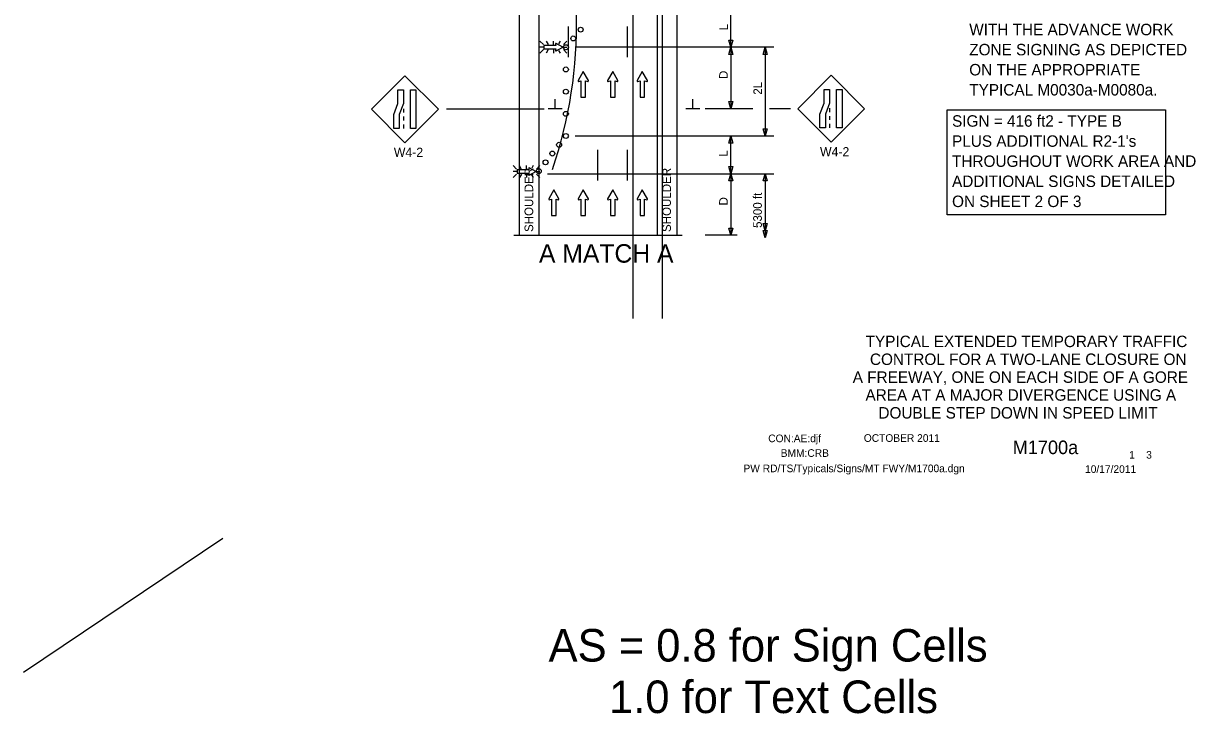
# Model space of a CAD drawing. Extents: x 16486 to 19505, y 5576 to 6998.
# Drawn here: x 16486 to 17438, y 5738 to 6298 of the extents above; entities that cross this region are included whole.
import ezdxf

# ---------------------------------------------------------------- set-up
doc = ezdxf.new("R2010")
doc.units = 0
for name, color, linetype in [('ALI_LEGAL_EX', 7, 'Continuous'), ('BORDER', 7, 'Continuous'), ('BORDER_SIGNAL_WO', 7, 'Continuous'), ('MT_SCRATCH_LEVEL_E', 7, 'Continuous'), ('PAVT_EDGE_EX', 7, 'Continuous'), ('TRAFFIC_SIGNS_PR', 7, 'Continuous'), ('TYPICAL_TEXT_DIMEN_EX', 7, 'Continuous'), ('TYPICAL_TEXT_DIMEN_PR', 7, 'Continuous')]:
    doc.layers.add(name, color=color, linetype=linetype)

msp = doc.modelspace()

# ---------------------------------------------------------------- linework, layer by layer
at = {"layer": 'ALI_LEGAL_EX'}
for p, q in [((16980.68, 6974.12), (16980.68, 6155.98)), ((17004.68, 6974.12), (17004.68, 6155.98)), ((16980.68, 6922.21), (16980.68, 6058.3)), ((17004.68, 6922.21), (17004.68, 6058.3))]:
    msp.add_line(p, q, dxfattribs=at)
for points in [[(16928.4, 6270.33), (16928.4, 6295.33)], [(16976.4, 6270.33), (16976.4, 6295.33)], [(16952.4, 6170.33), (16952.4, 6195.33)], [(16976.4, 6170.33), (16976.4, 6195.33)]]:
    msp.add_lwpolyline(points, dxfattribs=at)
msp.add_arc((16571.06, 6296.99), 364, 341.14744, 21.33821, dxfattribs=at)
at = {"layer": 'MT_SCRATCH_LEVEL_E'}
for p, q in [((16940.5, 6258.7), (16936.39, 6251.46)), ((16944.64, 6251.46), (16940.5, 6258.7)), ((16964.4, 6258.7), (16960.29, 6251.46)), ((16968.55, 6251.46), (16964.4, 6258.7)), ((16988.45, 6258.7), (16984.34, 6251.46)), ((16992.6, 6251.46), (16988.45, 6258.7)), ((16936.87, 6250.78), (16938.64, 6251.09)), ((16938.64, 6251.09), (16938.64, 6237.84)), ((16942.39, 6237.84), (16942.39, 6251.09)), ((16942.39, 6251.09), (16944.16, 6250.78)), ((16960.77, 6250.78), (16962.55, 6251.09)), ((16962.55, 6251.09), (16962.55, 6237.84)), ((16966.29, 6237.84), (16966.29, 6251.09)), ((16966.29, 6251.09), (16968.07, 6250.78)), ((16984.82, 6250.78), (16986.6, 6251.09)), ((16986.6, 6251.09), (16986.6, 6237.84)), ((16990.34, 6237.84), (16990.34, 6251.09)), ((16990.34, 6251.09), (16992.12, 6250.78)), ((16938.64, 6237.84), (16942.39, 6237.84)), ((16962.55, 6237.84), (16966.29, 6237.84)), ((16986.6, 6237.84), (16990.34, 6237.84)), ((16916.59, 6162.72), (16912.48, 6155.48)), ((16920.74, 6155.48), (16916.59, 6162.72)), ((16940.5, 6162.72), (16936.39, 6155.48)), ((16944.64, 6155.48), (16940.5, 6162.72)), ((16964.4, 6162.72), (16960.29, 6155.48)), ((16968.55, 6155.48), (16964.4, 6162.72)), ((16988.45, 6162.72), (16984.34, 6155.48)), ((16992.6, 6155.48), (16988.45, 6162.72)), ((16912.96, 6154.79), (16914.74, 6155.11)), ((16914.74, 6155.11), (16914.74, 6141.85)), ((16918.48, 6141.85), (16918.48, 6155.11)), ((16918.48, 6155.11), (16920.26, 6154.79)), ((16936.87, 6154.79), (16938.64, 6155.11)), ((16938.64, 6155.11), (16938.64, 6141.85)), ((16942.39, 6141.85), (16942.39, 6155.11)), ((16942.39, 6155.11), (16944.16, 6154.79)), ((16960.77, 6154.79), (16962.55, 6155.11)), ((16962.55, 6155.11), (16962.55, 6141.85)), ((16966.29, 6141.85), (16966.29, 6155.11)), ((16966.29, 6155.11), (16968.07, 6154.79)), ((16984.82, 6154.79), (16986.6, 6155.11)), ((16986.6, 6155.11), (16986.6, 6141.85)), ((16990.34, 6141.85), (16990.34, 6155.11)), ((16990.34, 6155.11), (16992.12, 6154.79)), ((16914.74, 6141.85), (16918.48, 6141.85)), ((16938.64, 6141.85), (16942.39, 6141.85)), ((16962.55, 6141.85), (16966.29, 6141.85)), ((16986.6, 6141.85), (16990.34, 6141.85))]:
    msp.add_line(p, q, dxfattribs=at)
for centre, start, end in [((16936.79, 6251.24), 150.42484, 279.96381), ((16944.23, 6251.24), 260.03619, 29.77312), ((16960.7, 6251.24), 150.42484, 279.96381), ((16968.14, 6251.24), 260.03619, 29.77312), ((16984.75, 6251.24), 150.42484, 279.96381), ((16992.19, 6251.24), 260.03619, 29.77312), ((16912.89, 6155.25), 150.42484, 279.96381), ((16920.33, 6155.25), 260.03619, 29.77312), ((16936.79, 6155.25), 150.42484, 279.96381), ((16944.23, 6155.25), 260.03619, 29.77312), ((16960.7, 6155.25), 150.42484, 279.96381), ((16968.14, 6155.25), 260.03619, 29.77312), ((16984.75, 6155.25), 150.42484, 279.96381), ((16992.19, 6155.25), 260.03619, 29.77312)]:
    msp.add_arc(centre, 0.463, start, end, dxfattribs=at)
at = {"layer": 'PAVT_EDGE_EX'}
for p, q in [((16888.4, 6480.53), (16888.4, 6125.9)), ((16904.4, 6480.53), (16904.4, 6125.9)), ((17000.4, 6480.53), (17000.4, 6125.9)), ((17016.4, 6480.53), (17016.4, 6125.9))]:
    msp.add_line(p, q, dxfattribs=at)
at = {"layer": 'TRAFFIC_SIGNS_PR'}
for p, q in [((16908.17, 6280.57), (16905.35, 6283.39)), ((16910.47, 6283.39), (16912.1, 6280.57)), ((16916.26, 6280.57), (16916.26, 6283.39)), ((16921.73, 6283.39), (16920.52, 6281.3)), ((16927.16, 6283.39), (16924.35, 6280.57)), ((16908.17, 6278.54), (16905.35, 6278.54)), ((16908.17, 6276.51), (16905.35, 6273.69)), ((16912.12, 6276.51), (16910.5, 6273.69)), ((16916.26, 6276.51), (16916.26, 6273.69)), ((16920.44, 6275.87), (16921.7, 6273.69)), ((16924.35, 6278.54), (16927.16, 6278.54)), ((16927.16, 6273.69), (16924.35, 6276.51)), ((16795.76, 6255.3), (16768.61, 6228.14)), ((16822.91, 6228.14), (16795.76, 6255.3)), ((17141.78, 6255.72), (17114.62, 6228.57)), ((17168.93, 6228.57), (17141.78, 6255.72)), ((16768.61, 6228.14), (16795.76, 6200.99)), ((16794.51, 6228.64), (16794.51, 6225.44)), ((16795.76, 6200.99), (16822.91, 6228.14)), ((17114.62, 6228.57), (17141.78, 6201.41)), ((17140.53, 6229.06), (17140.53, 6225.86)), ((17141.78, 6201.41), (17168.93, 6228.57)), ((16794.51, 6222.24), (16794.51, 6219.04)), ((16794.51, 6215.84), (16794.51, 6212.64)), ((17140.53, 6222.66), (17140.53, 6219.46)), ((17140.53, 6216.26), (17140.53, 6213.06)), ((16886.3, 6179.62), (16883.48, 6182.44)), ((16886.3, 6177.59), (16883.48, 6177.59)), ((16888.6, 6182.44), (16890.23, 6179.62)), ((16894.39, 6179.62), (16894.39, 6182.44)), ((16899.86, 6182.44), (16898.65, 6180.35)), ((16905.29, 6182.44), (16902.47, 6179.62)), ((16902.47, 6177.59), (16905.29, 6177.59)), ((16886.3, 6175.56), (16883.48, 6172.74)), ((16890.25, 6175.56), (16888.62, 6172.74)), ((16894.39, 6175.56), (16894.39, 6172.74)), ((16898.57, 6174.92), (16899.83, 6172.74)), ((16905.29, 6172.74), (16902.47, 6175.56))]:
    msp.add_line(p, q, dxfattribs=at)
for points in [[(16918.09, 6281.22), (16918.32, 6279.93), (16908.59, 6279.93), (16908.59, 6277.18), (16918.32, 6277.18), (16918.08, 6275.88)], [(16918.59, 6275.53), (16923.9, 6278.54), (16918.59, 6281.58)], [(16896.21, 6180.27), (16896.44, 6178.97), (16886.72, 6178.97), (16886.72, 6176.23), (16896.44, 6176.23), (16896.21, 6174.93)], [(16896.71, 6174.57), (16902.02, 6177.59), (16896.71, 6180.63)]]:
    msp.add_lwpolyline(points, dxfattribs=at)
for points in [[(16794.51, 6243.88), (16794.51, 6232.7), (16791.17, 6223.82), (16791.17, 6212.64), (16786.67, 6212.64), (16786.67, 6223.82), (16790.02, 6232.7), (16790.02, 6243.88)], [(16804.65, 6243.88), (16804.65, 6212.64), (16800.15, 6212.64), (16800.15, 6243.88)], [(17140.53, 6244.3), (17140.53, 6233.12), (17137.19, 6224.24), (17137.19, 6213.06), (17132.69, 6213.06), (17132.69, 6224.24), (17136.04, 6233.12), (17136.04, 6244.3)], [(17150.67, 6244.3), (17150.67, 6213.06), (17146.17, 6213.06), (17146.17, 6244.3)]]:
    msp.add_lwpolyline(points, close=True, dxfattribs=at)
for centre in [(16938.4, 6292.75), (16932.4, 6285.61), (16926.4, 6278.47), (16926.4, 6260.47), (16926.4, 6242.47), (16926.4, 6224.47), (16926.4, 6206.47), (16920.9, 6199.34), (16909.91, 6185.08), (16915.4, 6192.21), (16904.41, 6177.96)]:
    msp.add_circle(centre, 2, dxfattribs=at)
for centre, start, end in [((16918.42, 6281.28), 61.48329, 189.95933), ((16918.42, 6275.82), 170.73078, 298.89165), ((16896.55, 6180.33), 61.48329, 189.95933), ((16896.55, 6174.87), 170.73078, 298.89165)]:
    msp.add_arc(centre, 0.341, start, end, dxfattribs=at)
at = {"layer": 'TYPICAL_TEXT_DIMEN_EX'}
msp.add_lwpolyline([(17235.9, 6227.83), (17413.17, 6227.83), (17413.17, 6142.51), (17235.9, 6142.51)], close=True, dxfattribs=at)
at = {"layer": 'TYPICAL_TEXT_DIMEN_PR'}
for p, q in [((17060.4, 6278.47), (17060.4, 6307.03)), ((17060.4, 6278.47), (17058.83, 6284.33)), ((17058.83, 6284.33), (17060.4, 6284.33)), ((17060.4, 6284.33), (17061.97, 6284.33)), ((17061.97, 6284.33), (17060.4, 6278.47)), ((17095.19, 6278.47), (16933.9, 6278.47)), ((17058.83, 6272.61), (17060.4, 6278.47)), ((17060.4, 6272.61), (17058.83, 6272.61)), ((17060.4, 6278.47), (17060.4, 6228.47)), ((17060.4, 6278.47), (17061.97, 6272.61)), ((17061.97, 6272.61), (17060.4, 6272.61)), ((17086.64, 6272.61), (17088.21, 6278.47)), ((17088.21, 6272.61), (17086.64, 6272.61)), ((17088.21, 6278.47), (17089.78, 6272.61)), ((17088.21, 6278.47), (17088.21, 6206.47)), ((17089.78, 6272.61), (17088.21, 6272.61)), ((16917.69, 6228.47), (16917.69, 6236.25)), ((17029.53, 6228.47), (17029.53, 6236.25)), ((17060.4, 6228.47), (17058.83, 6234.33)), ((17058.83, 6234.33), (17060.4, 6234.33)), ((17060.4, 6234.33), (17061.97, 6234.33)), ((17061.97, 6234.33), (17060.4, 6228.47)), ((16829.5, 6228.47), (16908.69, 6228.47)), ((16923.31, 6228.47), (16912.06, 6228.47)), ((17035.15, 6228.47), (17023.9, 6228.47)), ((17078.18, 6228.47), (17039.4, 6228.47)), ((17108.81, 6228.47), (17091.83, 6228.47)), ((16933.9, 6206.47), (17095.19, 6206.47)), ((17058.83, 6200.61), (17060.4, 6206.47)), ((17060.4, 6175.9), (17060.4, 6206.47)), ((17060.4, 6206.47), (17061.97, 6200.61)), ((17088.21, 6206.47), (17086.64, 6212.33)), ((17086.64, 6212.33), (17088.21, 6212.33)), ((17088.21, 6212.33), (17089.78, 6212.33)), ((17089.78, 6212.33), (17088.21, 6206.47)), ((17060.4, 6200.61), (17058.83, 6200.61)), ((17061.97, 6200.61), (17060.4, 6200.61)), ((17060.4, 6175.9), (17058.83, 6181.77)), ((17058.83, 6181.77), (17060.4, 6181.77)), ((17060.4, 6181.77), (17061.97, 6181.77)), ((17061.97, 6181.77), (17060.4, 6175.9)), ((16911.36, 6175.9), (17095.19, 6175.9)), ((17058.83, 6170.04), (17060.4, 6175.9)), ((17060.4, 6170.04), (17058.83, 6170.04)), ((17060.4, 6175.9), (17060.4, 6125.9)), ((17060.4, 6175.9), (17061.97, 6170.04)), ((17061.97, 6170.04), (17060.4, 6170.04)), ((17086.64, 6170.04), (17088.21, 6175.9)), ((17088.21, 6170.04), (17086.64, 6170.04)), ((17088.21, 6175.9), (17088.21, 6125.9)), ((17088.21, 6175.9), (17089.78, 6170.04)), ((17089.78, 6170.04), (17088.21, 6170.04)), ((17060.4, 6125.9), (17058.83, 6131.77)), ((17058.83, 6131.77), (17060.4, 6131.77)), ((17060.4, 6131.77), (17061.97, 6131.77)), ((17061.97, 6131.77), (17060.4, 6125.9)), ((17088.21, 6129.64), (17086.64, 6135.5)), ((17086.64, 6135.5), (17088.21, 6135.5)), ((17088.21, 6123.86), (17086.64, 6129.72)), ((17086.64, 6129.72), (17088.21, 6129.72)), ((17088.21, 6135.5), (17089.78, 6135.5)), ((17089.78, 6135.5), (17088.21, 6129.64)), ((17088.21, 6129.72), (17089.78, 6129.72)), ((17089.78, 6129.72), (17088.21, 6123.86)), ((16884.1, 6125.9), (17020.75, 6125.9)), ((17065.4, 6125.9), (17039.4, 6125.9)), ((16647.75, 5880), (16485.98, 5771.23))]:
    msp.add_line(p, q, dxfattribs=at)

# ---------------------------------------------------------------- texts
at = {"layer": 'BORDER'}
for s, p in [('TYPICAL EXTENDED TEMPORARY TRAFFIC', (17169.79, 6035.19)), ('CONTROL FOR A TWO-LANE CLOSURE ON', (17173.28, 6020.7)), ('A FREEWAY, ONE ON EACH SIDE OF A GORE', (17159.3, 6006.21)), ('AREA AT A MAJOR DIVERGENCE USING A', (17169.66, 5991.71)), ('DOUBLE STEP DOWN IN SPEED LIMIT', (17180.16, 5977.22))]:
    msp.add_text(s, height=9.3, dxfattribs=at).set_placement(p)
at = {"layer": 'BORDER_SIGNAL_WO'}
for s, height, p in [('CON:AE:djf  ', 6.2, (17090.69, 5958.06)), ('    OCTOBER 2011', 6.2, (17159.08, 5958.34)), ('    M1700a   ', 11, (17272.86, 5948.38)), ('BMM:CRB', 6.2, (17100.81, 5946.17)), (' 1    3 ', 6.2, (17381.45, 5944.7)), ('PW RD/TS/Typicals/Signs/MT FWY/M1700a.dgn      ', 6.2, (17070.55, 5933.71)), ('10/17/2011', 6.2, (17347.93, 5933.13)), ('AS = 0.8 for Sign Cells', 26.4241, (16912.35, 5780.08)), ('     1.0 for Text Cells', 26.4241, (16912.35, 5738.29))]:
    msp.add_text(s, height=height, dxfattribs=at).set_placement(p)
at = {"layer": 'TRAFFIC_SIGNS_PR'}
for p in [(16786.72, 6189.55), (17132.73, 6189.98)]:
    msp.add_text('W4-2', height=7.44, dxfattribs=at).set_placement(p)
at = {"layer": 'TYPICAL_TEXT_DIMEN_EX'}
for s, p in [('WITH THE ADVANCE WORK', (17253.92, 6288.21)), ('ZONE SIGNING AS DEPICTED', (17253.92, 6271.91)), ('ON THE APPROPRIATE', (17253.92, 6255.61)), ('TYPICAL M0030a-M0080a.', (17253.92, 6239.31)), ('SIGN = 416 ft2 - TYPE B', (17239.95, 6214)), ("PLUS ADDITIONAL R2-1's", (17239.95, 6197.7)), ('THROUGHOUT WORK AREA AND', (17239.95, 6181.4)), ('ADDITIONAL SIGNS DETAILED', (17239.95, 6165.1)), ('ON SHEET 2 OF 3', (17239.95, 6148.8))]:
    msp.add_text(s, height=9.3, dxfattribs=at).set_placement(p)
at = {"layer": 'TYPICAL_TEXT_DIMEN_PR'}
for s, p in [('L', (17057.93, 6292.11)), ('D', (17057.84, 6252.69)), ('2L', (17085.65, 6239.97)), ('L', (17057.84, 6189.76)), ('SHOULDER', (16899.84, 6128.61)), ('SHOULDER', (17011.7, 6128.61)), ('5300 ft', (17085.5, 6131.86)), ('D', (17057.84, 6150.12))]:
    msp.add_text(s, height=7, rotation=90, dxfattribs=at).set_placement(p)
msp.add_text('A MATCH A', height=15, dxfattribs=at).set_placement((16904.56, 6103.71))

doc.saveas('drawing.dxf')
